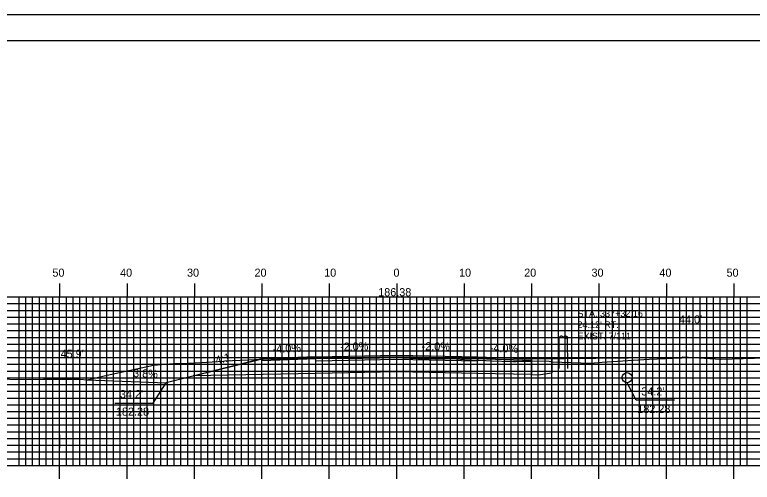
# Model space of a CAD drawing. Extents: x 1823571 to 1823914, y 442310 to 442530.
# Drawn here: x 1823680.2 to 1823789.6, y 442460.6 to 442530 of the extents above; entities that cross this region are included whole.
import ezdxf

# ---------------------------------------------------------------- set-up
doc = ezdxf.new("R2010")
doc.units = 0
for name, color, linetype in [('ANNOTATION', 7, 'Continuous'), ('BORDER', 7, 'Continuous'), ('D_Drainage_Culvert', 7, 'Continuous'), ('D_Roadway_Centerline', 7, 'Continuous'), ('D_Roadway_Centerline_Text', 7, 'Continuous'), ('D_Roadway_Drive_SubGrade', 7, 'Continuous'), ('D_Roadway_Edge_Shoulder', 7, 'Continuous'), ('D_Roadway_Edge_TW', 7, 'Continuous'), ('D_Roadway_Pavement', 7, 'Continuous'), ('D_Roadway_SlopeLines', 7, 'Continuous'), ('D_Roadway_SubGrade', 7, 'Continuous'), ('D_Text_Monospaced', 7, 'Continuous'), ('D_Text_Standard', 7, 'Continuous'), ('H_V ANNOTATION', 7, 'Continuous'), ('MAJOR', 7, 'Continuous'), ('MINOR', 7, 'Continuous'), ('PLOT BOUNDARY', 7, 'Continuous'), ('S_Roadway_Centerline', 7, 'Continuous'), ('S_Utilities_Pole_Power', 7, 'Continuous')]:
    doc.layers.add(name, color=color, linetype=linetype)

msp = doc.modelspace()

# ---------------------------------------------------------------- linework, layer by layer
at = {"layer": 'ANNOTATION'}
for points in [[(1823695.11, 442472.38), (1823700.8, 442472.38), (1823702.73, 442475.39)], [(1823778.13, 442472.78), (1823772.44, 442472.78), (1823771.07, 442475.39)]]:
    msp.add_lwpolyline(points, dxfattribs=at)
at = {"layer": 'BORDER'}
msp.add_lwpolyline([(1823587.3, 442316.11), (1823907.3, 442316.11), (1823907.3, 442526.11), (1823587.3, 442526.11)], close=True, dxfattribs=at)
at = {"layer": 'D_Drainage_Culvert'}
msp.add_circle((1823771.07, 442476.14), 0.75, dxfattribs=at)
at = {"layer": 'D_Roadway_Centerline'}
msp.add_lwpolyline([(1823706.73, 442476.39), (1823716.53, 442478.84), (1823716.9, 442478.93), (1823724.9, 442479.25), (1823736.9, 442479.49), (1823748.9, 442479.25), (1823756.9, 442478.93)], dxfattribs=at)
at = {"layer": 'D_Roadway_Drive_SubGrade'}
for p, q in [((1823756.9, 442476.59), (1823757.9, 442476.58)), ((1823757.9, 442476.58), (1823759.9, 442476.87))]:
    msp.add_line(p, q, dxfattribs=at)
at = {"layer": 'D_Roadway_Edge_Shoulder'}
for points in [[(1823724.9, 442479.25), (1823716.9, 442478.93), (1823716.9, 442478.68), (1823724.9, 442479)], [(1823748.9, 442479.25), (1823756.9, 442478.93), (1823756.9, 442478.68), (1823748.9, 442479)]]:
    msp.add_lwpolyline(points, close=True, dxfattribs=at)
at = {"layer": 'D_Roadway_Edge_TW'}
msp.add_lwpolyline([(1823724.9, 442479), (1823724.9, 442479.25), (1823736.9, 442479.49), (1823748.9, 442479.25), (1823748.9, 442479), (1823736.9, 442479.24)], close=True, dxfattribs=at)
at = {"layer": 'D_Roadway_Pavement'}
msp.add_lwpolyline([(1823724.9, 442478.59), (1823724.9, 442479), (1823736.9, 442479.24), (1823748.9, 442479), (1823748.9, 442478.59), (1823736.9, 442478.83)], close=True, dxfattribs=at)
at = {"layer": 'D_Roadway_SlopeLines'}
for p in [(1823716.9, 442478.93), (1823690.98, 442475.84)]:
    msp.add_line(p, (1823702.73, 442475.39), dxfattribs=at)
msp.add_lwpolyline([(1823716.9, 442478.93), (1823716.53, 442478.84)], dxfattribs=at)
at = {"layer": 'D_Roadway_SubGrade'}
msp.add_lwpolyline([(1823756.9, 442476.59), (1823748.9, 442476.75), (1823736.9, 442476.99), (1823724.9, 442476.75), (1823706.73, 442476.39), (1823716.9, 442478.93), (1823716.9, 442478.68), (1823724.9, 442479), (1823736.9, 442479.24), (1823748.9, 442479), (1823756.9, 442478.68), (1823756.9, 442478.93)], dxfattribs=at)
at = {"layer": 'D_Text_Standard'}
for p, q in [((1823756.9, 442478.93), (1823780.79, 442479.16)), ((1823756.9, 442478.93), (1823756.9, 442476.59)), ((1823759.9, 442478.93), (1823759.9, 442478.96)), ((1823759.9, 442478.96), (1823759.9, 442476.87))]:
    msp.add_line(p, q, dxfattribs=at)
at = {"layer": 'MAJOR'}
for p, q in [((1823686.9, 442490.12), (1823686.9, 442488.12)), ((1823696.9, 442490.12), (1823696.9, 442488.12)), ((1823706.9, 442490.12), (1823706.9, 442488.12)), ((1823716.9, 442490.12), (1823716.9, 442488.12)), ((1823726.9, 442490.12), (1823726.9, 442488.12)), ((1823736.9, 442490.12), (1823736.9, 442488.12)), ((1823746.9, 442490.12), (1823746.9, 442488.12)), ((1823756.9, 442490.12), (1823756.9, 442488.12)), ((1823766.9, 442490.12), (1823766.9, 442488.12)), ((1823776.9, 442490.12), (1823776.9, 442488.12)), ((1823786.9, 442490.12), (1823786.9, 442488.12)), ((1823596.9, 442488.12), (1823876.9, 442488.12)), ((1823596.9, 442488.12), (1823876.9, 442488.12)), ((1823686.9, 442463.12), (1823686.9, 442488.12)), ((1823696.9, 442463.12), (1823696.9, 442488.12)), ((1823706.9, 442463.12), (1823706.9, 442488.12)), ((1823716.9, 442463.12), (1823716.9, 442488.12)), ((1823726.9, 442463.12), (1823726.9, 442488.12)), ((1823736.9, 442463.12), (1823736.9, 442488.12)), ((1823746.9, 442463.12), (1823746.9, 442488.12)), ((1823756.9, 442463.12), (1823756.9, 442488.12)), ((1823766.9, 442463.12), (1823766.9, 442488.12)), ((1823776.9, 442463.12), (1823776.9, 442488.12)), ((1823786.9, 442463.12), (1823786.9, 442488.12)), ((1823596.9, 442483.12), (1823876.9, 442483.12)), ((1823596.9, 442478.12), (1823876.9, 442478.12)), ((1823596.9, 442473.12), (1823876.9, 442473.12)), ((1823596.9, 442468.12), (1823876.9, 442468.12)), ((1823686.9, 442467.68), (1823686.9, 442465.68)), ((1823596.9, 442463.12), (1823876.9, 442463.12)), ((1823596.9, 442463.12), (1823876.9, 442463.12)), ((1823686.9, 442461.11), (1823686.9, 442463.12)), ((1823696.9, 442461.11), (1823696.9, 442463.12)), ((1823706.9, 442461.11), (1823706.9, 442463.12)), ((1823716.9, 442461.11), (1823716.9, 442463.12)), ((1823726.9, 442461.11), (1823726.9, 442463.12)), ((1823736.9, 442461.11), (1823736.9, 442463.12)), ((1823746.9, 442461.11), (1823746.9, 442463.12)), ((1823756.9, 442461.11), (1823756.9, 442463.12)), ((1823766.9, 442461.11), (1823766.9, 442463.12)), ((1823776.9, 442461.11), (1823776.9, 442463.12)), ((1823786.9, 442461.11), (1823786.9, 442463.12))]:
    msp.add_line(p, q, dxfattribs=at)
at = {"layer": 'MINOR'}
for p, q in [((1823680.9, 442463.12), (1823680.9, 442488.12)), ((1823681.9, 442463.12), (1823681.9, 442488.12)), ((1823682.9, 442463.12), (1823682.9, 442488.12)), ((1823683.9, 442463.12), (1823683.9, 442488.12)), ((1823684.9, 442463.12), (1823684.9, 442488.12)), ((1823685.9, 442463.12), (1823685.9, 442488.12)), ((1823687.9, 442463.12), (1823687.9, 442488.12)), ((1823688.9, 442463.12), (1823688.9, 442488.12)), ((1823689.9, 442463.12), (1823689.9, 442488.12)), ((1823690.9, 442463.12), (1823690.9, 442488.12)), ((1823691.9, 442463.12), (1823691.9, 442488.12)), ((1823692.9, 442463.12), (1823692.9, 442488.12)), ((1823693.9, 442463.12), (1823693.9, 442488.12)), ((1823694.9, 442463.12), (1823694.9, 442488.12)), ((1823695.9, 442463.12), (1823695.9, 442488.12)), ((1823697.9, 442463.12), (1823697.9, 442488.12)), ((1823698.9, 442463.12), (1823698.9, 442488.12)), ((1823699.9, 442463.12), (1823699.9, 442488.12)), ((1823700.9, 442463.12), (1823700.9, 442488.12)), ((1823701.9, 442463.12), (1823701.9, 442488.12)), ((1823702.9, 442463.12), (1823702.9, 442488.12)), ((1823703.9, 442463.12), (1823703.9, 442488.12)), ((1823704.9, 442463.12), (1823704.9, 442488.12)), ((1823705.9, 442463.12), (1823705.9, 442488.12)), ((1823707.9, 442463.12), (1823707.9, 442488.12)), ((1823708.9, 442463.12), (1823708.9, 442488.12)), ((1823709.9, 442463.12), (1823709.9, 442488.12)), ((1823710.9, 442463.12), (1823710.9, 442488.12)), ((1823711.9, 442463.12), (1823711.9, 442488.12)), ((1823712.9, 442463.12), (1823712.9, 442488.12)), ((1823713.9, 442463.12), (1823713.9, 442488.12)), ((1823714.9, 442463.12), (1823714.9, 442488.12)), ((1823715.9, 442463.12), (1823715.9, 442488.12)), ((1823717.9, 442463.12), (1823717.9, 442488.12)), ((1823718.9, 442463.12), (1823718.9, 442488.12)), ((1823719.9, 442463.12), (1823719.9, 442488.12)), ((1823720.9, 442463.12), (1823720.9, 442488.12)), ((1823721.9, 442463.12), (1823721.9, 442488.12)), ((1823722.9, 442463.12), (1823722.9, 442488.12)), ((1823723.9, 442463.12), (1823723.9, 442488.12)), ((1823724.9, 442463.12), (1823724.9, 442488.12)), ((1823725.9, 442463.12), (1823725.9, 442488.12)), ((1823727.9, 442463.12), (1823727.9, 442488.12)), ((1823728.9, 442463.12), (1823728.9, 442488.12)), ((1823729.9, 442463.12), (1823729.9, 442488.12)), ((1823730.9, 442463.12), (1823730.9, 442488.12)), ((1823731.9, 442463.12), (1823731.9, 442488.12)), ((1823732.9, 442463.12), (1823732.9, 442488.12)), ((1823733.9, 442463.12), (1823733.9, 442488.12)), ((1823734.9, 442463.12), (1823734.9, 442488.12)), ((1823735.9, 442463.12), (1823735.9, 442488.12)), ((1823737.9, 442463.12), (1823737.9, 442488.12)), ((1823738.9, 442463.12), (1823738.9, 442488.12)), ((1823739.9, 442463.12), (1823739.9, 442488.12)), ((1823740.9, 442463.12), (1823740.9, 442488.12)), ((1823741.9, 442463.12), (1823741.9, 442488.12)), ((1823742.9, 442463.12), (1823742.9, 442488.12)), ((1823743.9, 442463.12), (1823743.9, 442488.12)), ((1823744.9, 442463.12), (1823744.9, 442488.12)), ((1823745.9, 442463.12), (1823745.9, 442488.12)), ((1823747.9, 442463.12), (1823747.9, 442488.12)), ((1823748.9, 442463.12), (1823748.9, 442488.12)), ((1823749.9, 442463.12), (1823749.9, 442488.12)), ((1823750.9, 442463.12), (1823750.9, 442488.12)), ((1823751.9, 442463.12), (1823751.9, 442488.12)), ((1823752.9, 442463.12), (1823752.9, 442488.12)), ((1823753.9, 442463.12), (1823753.9, 442488.12)), ((1823754.9, 442463.12), (1823754.9, 442488.12)), ((1823755.9, 442463.12), (1823755.9, 442488.12)), ((1823757.9, 442463.12), (1823757.9, 442488.12)), ((1823758.9, 442463.12), (1823758.9, 442488.12)), ((1823759.9, 442463.12), (1823759.9, 442488.12)), ((1823760.9, 442463.12), (1823760.9, 442488.12)), ((1823761.9, 442463.12), (1823761.9, 442488.12)), ((1823762.9, 442463.12), (1823762.9, 442488.12)), ((1823763.9, 442463.12), (1823763.9, 442488.12)), ((1823764.9, 442463.12), (1823764.9, 442488.12)), ((1823765.9, 442463.12), (1823765.9, 442488.12)), ((1823767.9, 442463.12), (1823767.9, 442488.12)), ((1823768.9, 442463.12), (1823768.9, 442488.12)), ((1823769.9, 442463.12), (1823769.9, 442488.12)), ((1823770.9, 442463.12), (1823770.9, 442488.12)), ((1823771.9, 442463.12), (1823771.9, 442488.12)), ((1823772.9, 442463.12), (1823772.9, 442488.12)), ((1823773.9, 442463.12), (1823773.9, 442488.12)), ((1823774.9, 442463.12), (1823774.9, 442488.12)), ((1823775.9, 442463.12), (1823775.9, 442488.12)), ((1823777.9, 442463.12), (1823777.9, 442488.12)), ((1823778.9, 442463.12), (1823778.9, 442488.12)), ((1823779.9, 442463.12), (1823779.9, 442488.12)), ((1823780.9, 442463.12), (1823780.9, 442488.12)), ((1823781.9, 442463.12), (1823781.9, 442488.12)), ((1823782.9, 442463.12), (1823782.9, 442488.12)), ((1823783.9, 442463.12), (1823783.9, 442488.12)), ((1823784.9, 442463.12), (1823784.9, 442488.12)), ((1823785.9, 442463.12), (1823785.9, 442488.12)), ((1823787.9, 442463.12), (1823787.9, 442488.12)), ((1823788.9, 442463.12), (1823788.9, 442488.12)), ((1823596.9, 442487.12), (1823876.9, 442487.12)), ((1823596.9, 442486.12), (1823876.9, 442486.12)), ((1823596.9, 442485.12), (1823876.9, 442485.12)), ((1823596.9, 442484.12), (1823876.9, 442484.12)), ((1823596.9, 442482.12), (1823876.9, 442482.12)), ((1823596.9, 442481.12), (1823876.9, 442481.12)), ((1823596.9, 442480.12), (1823876.9, 442480.12)), ((1823596.9, 442479.12), (1823876.9, 442479.12)), ((1823596.9, 442477.12), (1823876.9, 442477.12)), ((1823596.9, 442476.12), (1823876.9, 442476.12)), ((1823596.9, 442475.12), (1823876.9, 442475.12)), ((1823596.9, 442474.12), (1823876.9, 442474.12)), ((1823596.9, 442472.12), (1823876.9, 442472.12)), ((1823596.9, 442471.12), (1823876.9, 442471.12)), ((1823596.9, 442470.12), (1823876.9, 442470.12)), ((1823596.9, 442469.12), (1823876.9, 442469.12)), ((1823596.9, 442467.12), (1823876.9, 442467.12)), ((1823596.9, 442466.12), (1823876.9, 442466.12)), ((1823596.9, 442465.12), (1823876.9, 442465.12)), ((1823596.9, 442464.12), (1823876.9, 442464.12))]:
    msp.add_line(p, q, dxfattribs=at)
at = {"layer": 'PLOT BOUNDARY'}
msp.add_lwpolyline([(1823571.11, 442309.99), (1823911.11, 442309.99), (1823911.11, 442529.99), (1823571.11, 442529.99)], close=True, dxfattribs=at)
at = {"layer": 'S_Roadway_Centerline'}
msp.add_lwpolyline([(1823675.04, 442475.99), (1823683.92, 442475.89), (1823684.49, 442475.92), (1823684.62, 442475.9), (1823689.24, 442475.94), (1823689.96, 442475.9), (1823690.98, 442475.84), (1823693.97, 442476.51), (1823700.83, 442478.01), (1823702.07, 442478.08), (1823703.72, 442478.25), (1823706.03, 442478.3), (1823707.01, 442478.33), (1823711.19, 442478.57), (1823711.43, 442478.64), (1823718.23, 442478.91), (1823722.4, 442478.95), (1823723.98, 442479.14), (1823725.52, 442479.04), (1823731.88, 442479.05), (1823736.88, 442479.15), (1823740.09, 442478.99), (1823742.72, 442478.93), (1823744.3, 442478.98), (1823745.76, 442478.92), (1823746.89, 442478.86), (1823750.12, 442478.7), (1823750.82, 442478.63), (1823754.11, 442478.53), (1823754.61, 442478.52), (1823758.97, 442478.64), (1823759.5, 442478.58), (1823759.99, 442478.5), (1823765.58, 442478.28), (1823767.4, 442478.46), (1823771.2, 442478.71), (1823774.35, 442478.9), (1823779.15, 442479.07), (1823779.35, 442479.25), (1823784.96, 442478.89), (1823791.65, 442479.08)], dxfattribs=at)
at = {"layer": 'S_Utilities_Pole_Power'}
for p, q in [((1823761.02, 442477.52), (1823761.01, 442482.14)), ((1823761.02, 442482.14), (1823761.17, 442482.25)), ((1823761.49, 442482.25), (1823761.64, 442482.14)), ((1823761.8, 442482.25), (1823761.64, 442482.14)), ((1823761.64, 442482.14), (1823761.8, 442482.03)), ((1823762.27, 442482.14), (1823762.11, 442482.25)), ((1823762.11, 442482.03), (1823762.27, 442482.14)), ((1823762.27, 442477.52), (1823762.26, 442482.14))]:
    msp.add_line(p, q, dxfattribs=at)
for centre, start, end in [((1823761.33, 442482.03), 90, 125.2644), ((1823761.33, 442482.03), 54.7356, 90), ((1823761.95, 442482.03), 90, 125.2644), ((1823761.95, 442482.25), 234.7356, 270), ((1823761.95, 442482.03), 54.7356, 90), ((1823761.95, 442482.25), 270, 305.2644)]:
    msp.add_arc(centre, 0.271, start, end, dxfattribs=at)

# ---------------------------------------------------------------- texts
at = {"layer": 'ANNOTATION'}
for s, rotation, p in [('-2.0%', 1.1458, (1823728.51, 442480.13)), ('-2.0%', 358.8542, (1823740.59, 442480.22)), ('-4.0%', 2.2906, (1823718.53, 442479.8)), ('-4.0%', 357.7094, (1823750.69, 442479.98)), ('4:1', 14.0362, (1823710.16, 442478.11)), ('3.8%', 357.8136, (1823697.79, 442476.23))]:
    msp.add_text(s, height=1.2, rotation=rotation, dxfattribs=at).set_placement(p)
for s, p in [("34.2'", (1823773.18, 442473.5)), ("34.2'", (1823695.84, 442473.1)), ('182.28', (1823695.26, 442470.5)), ('182.28', (1823772.59, 442470.9))]:
    msp.add_text(s, height=1.2, dxfattribs=at).set_placement(p)
at = {"layer": 'D_Roadway_Centerline'}
for s, p in [('C', (1823736.89, 442479.49)), ('L', (1823736.9, 442479.49))]:
    msp.add_text(s, height=0.0146, dxfattribs=at).set_placement(p)
at = {"layer": 'D_Roadway_Centerline_Text'}
msp.add_text('186.38', height=1.2, dxfattribs=at).set_placement((1823734.16, 442488.22))
at = {"layer": 'D_Text_Monospaced'}
for s, p in [('STA. 337+32.16', (1823763.72, 442485.16)), ("24.12' RT.", (1823763.72, 442483.49)), ('EXIST. 7/111', (1823763.72, 442481.81))]:
    msp.add_text(s, height=1, dxfattribs=at).set_placement(p)
at = {"layer": 'D_Text_Standard'}
for s, p in [("44.0'", (1823778.78, 442484.19)), ("45.9'", (1823687.05, 442479.09))]:
    msp.add_text(s, height=1.2, dxfattribs=at).set_placement(p)
at = {"layer": 'H_V ANNOTATION'}
for s, p in [('50', (1823685.83, 442491.12)), ('40', (1823695.87, 442491.12)), ('30', (1823705.8, 442491.12)), ('20', (1823715.81, 442491.12)), ('10', (1823726.15, 442491.12)), ('0', (1823736.42, 442491.12)), ('10', (1823746.15, 442491.12)), ('20', (1823755.81, 442491.12)), ('30', (1823765.8, 442491.12)), ('40', (1823775.87, 442491.12)), ('50', (1823785.83, 442491.12))]:
    msp.add_text(s, height=1.2, dxfattribs=at).set_placement(p)
at = {"layer": 'S_Roadway_Centerline'}
for s, p in [('C', (1823723.97, 442479.14)), ('L', (1823723.97, 442479.13))]:
    msp.add_text(s, height=0.0146, dxfattribs=at).set_placement(p)

doc.saveas('drawing.dxf')
